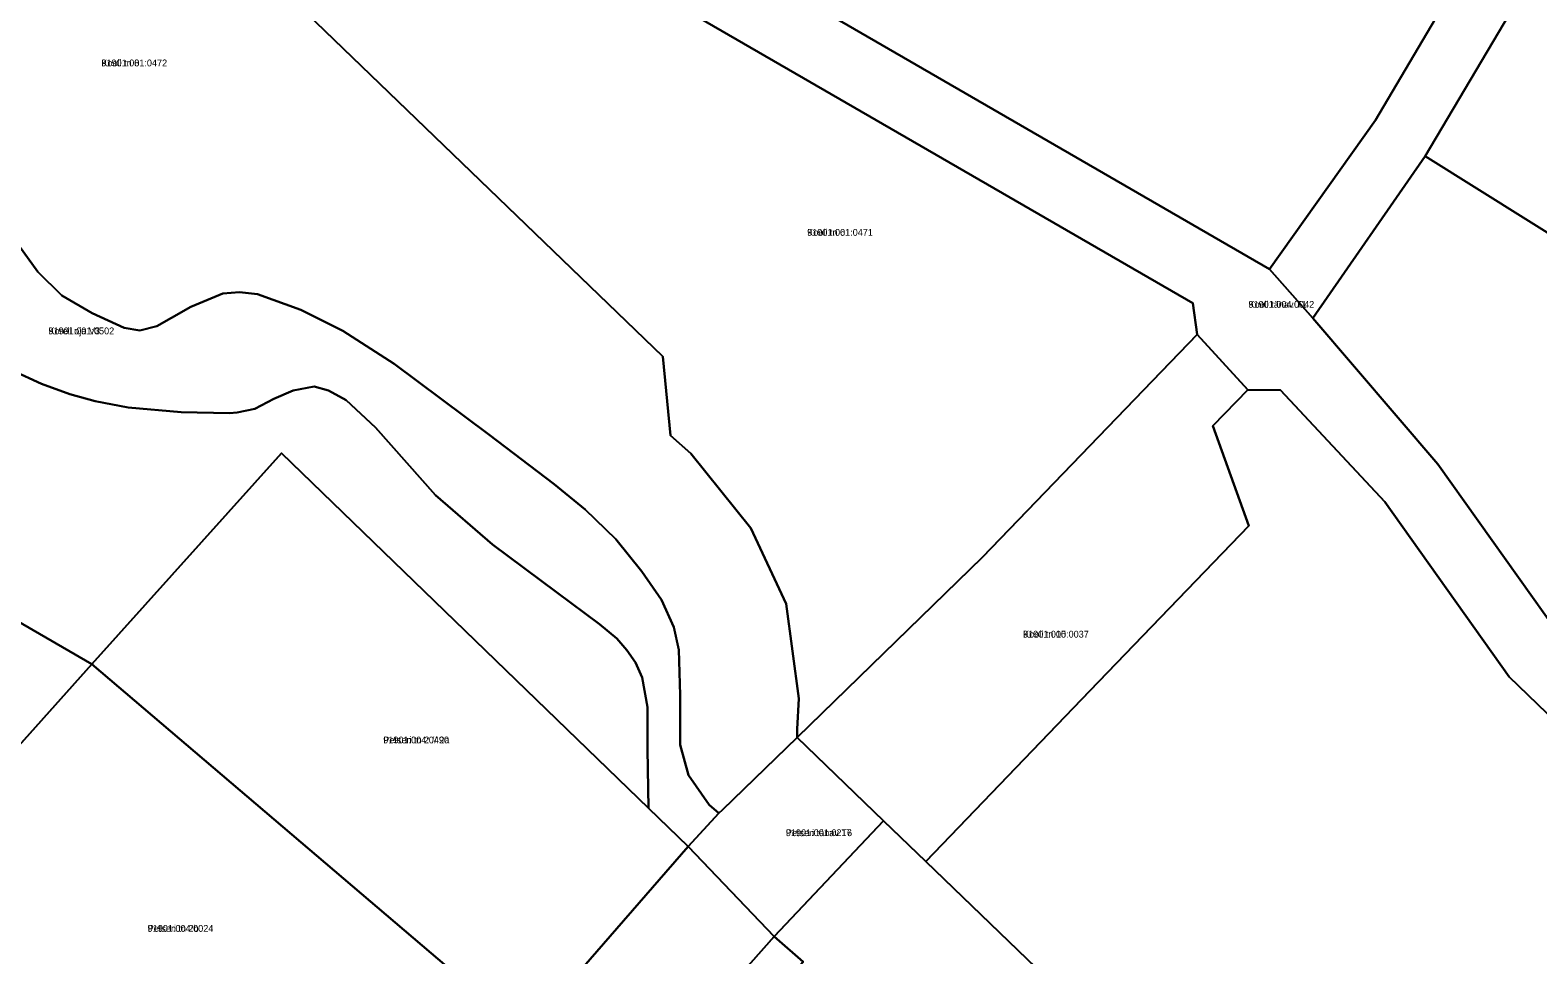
# Model space of a CAD drawing. Extents: x 675810 to 681273, y 6411190 to 6417565.
# Drawn here: x 678420.5 to 678753.1, y 6415433.8 to 6415637.7 of the extents above; entities that cross this region are included whole.
import ezdxf

# ---------------------------------------------------------------- set-up
doc = ezdxf.new("R2010")
doc.units = 0
for name, color, linetype in [('L_AADRESS', 7, 'Continuous'), ('PIIR', 7, 'Continuous'), ('TUNNUS', 7, 'Continuous')]:
    doc.layers.add(name, color=color, linetype=linetype)

msp = doc.modelspace()

# ---------------------------------------------------------------- linework, layer by layer
at = {"layer": 'PIIR'}
for points in [[(678717.31, 6415617.85), (678693.89, 6415584.98), (678536.61, 6415675.95), (678527.82, 6415691.55), (678599.64, 6415810.83), (678613.08, 6415812.33), (678614.18, 6415808.05), (678621.93, 6415778.52), (678657.45, 6415759.12), (678662.54, 6415756.35), (678693.95, 6415739.26), (678709.19, 6415730.96), (678765.39, 6415700.27), (678765.87, 6415700.01)], [(678459.31, 6415662.82), (678502.14, 6415702.96), (678522.6, 6415666.75), (678677, 6415577.51), (678677.93, 6415570.6), (678630.57, 6415521.46), (678589.7, 6415481.71), (678589.71, 6415483.49), (678590.11, 6415490.25), (678587.29, 6415511.18), (678579.49, 6415527.84), (678566.22, 6415544.29), (678561.73, 6415548.27), (678560.09, 6415565.74)], [(678765.87, 6415700.01), (678772.39, 6415696.39), (678777.6, 6415693.42), (678757.94, 6415660.15), (678783.06, 6415644.39), (678794.13, 6415637.17), (678787.76, 6415627.4), (678751.91, 6415649.88), (678728.29, 6415609.9), (678703.45, 6415574.17), (678693.89, 6415584.98), (678717.31, 6415617.85)], [(678751.91, 6415649.88), (678787.76, 6415627.4), (678762.45, 6415588.51), (678728.29, 6415609.9)], [(678728.29, 6415609.9), (678762.45, 6415588.51), (678793.29, 6415569.17), (678788.17, 6415560.57), (678766.76, 6415526.38), (678818.37, 6415494.02), (678799.97, 6415464.74), (678757.76, 6415504.49), (678731.08, 6415541.99), (678703.45, 6415574.17)], [(678677.93, 6415570.6), (678689.11, 6415558.37), (678681.42, 6415550.39), (678689.39, 6415528.39), (678654.27, 6415491.95), (678618.06, 6415454.35), (678608.76, 6415463.31), (678589.7, 6415481.71), (678630.57, 6415521.46)], [(678529.76, 6415416.4), (678434.11, 6415497.88), (678475.9, 6415544.38), (678556.91, 6415466.12), (678565.67, 6415457.65)], [(678402.16, 6415516.32), (678434.11, 6415497.88), (678405.4, 6415465.9), (678389.48, 6415480.64), (678381.04, 6415471.59), (678369.49, 6415483.78)], [(678434.11, 6415497.88), (678529.76, 6415416.4), (678497.75, 6415379.78), (678473.98, 6415399.41), (678456.97, 6415380.5), (678442.3, 6415393.23), (678424.47, 6415408.59), (678402.71, 6415427.34), (678384.39, 6415443.11), (678370.48, 6415455.37), (678368.05, 6415457.5), (678381.04, 6415471.59), (678389.48, 6415480.64), (678405.4, 6415465.9)], [(678589.7, 6415481.71), (678608.76, 6415463.31), (678584.63, 6415437.83), (678565.67, 6415457.65), (678572.45, 6415464.96), (678573.21, 6415465.7)], [(678584.63, 6415437.83), (678608.76, 6415463.31), (678618.06, 6415454.35), (678662.7, 6415411.33), (678659.2, 6415407.69), (678682.83, 6415382.78), (678788.36, 6415281.11), (678802.18, 6415256.98), (678673.64, 6415238.7), (678714.53, 6415285.6), (678721.11, 6415293.41), (678720.4, 6415306.05), (678710.92, 6415314.87), (678711.4, 6415315.4), (678675.46, 6415348.99), (678631.26, 6415386.89), (678595.98, 6415417.47), (678585.87, 6415405.7), (678577.83, 6415417.22), (678591.06, 6415432.23)], [(678565.67, 6415457.65), (678584.63, 6415437.83), (678571.47, 6415422.91), (678577.83, 6415417.22), (678585.87, 6415405.7), (678566.01, 6415382.6), (678560.85, 6415376.6), (678533.42, 6415400.18), (678488.18, 6415348.7), (678464.2, 6415322.7), (678452.22, 6415309.34), (678433.25, 6415288.62), (678405.25, 6415257.4), (678395.92, 6415265.33), (678410.29, 6415281.72), (678428.69, 6415301.59), (678442, 6415316.83), (678453.58, 6415329.69), (678458.78, 6415334.97), (678482.4, 6415362.13), (678497.75, 6415379.78), (678529.76, 6415416.4)], [(678571.47, 6415422.91), (678584.63, 6415437.83), (678591.06, 6415432.23), (678577.83, 6415417.22)]]:
    msp.add_lwpolyline(points, close=True, dxfattribs=at)
for points in [[(678536.61, 6415675.95), (678693.89, 6415584.98), (678703.45, 6415574.17), (678731.08, 6415541.99), (678757.76, 6415504.49)], [(678771.76, 6415471.03), (678746.79, 6415495.08), (678719.35, 6415533.64), (678696.36, 6415558.3), (678689.11, 6415558.37), (678677.93, 6415570.6), (678677, 6415577.51), (678522.6, 6415666.75)], [(678459.31, 6415662.82), (678560.09, 6415565.74), (678561.73, 6415548.27), (678566.22, 6415544.29), (678579.49, 6415527.84), (678587.29, 6415511.18), (678590.11, 6415490.25), (678589.71, 6415483.49), (678589.7, 6415481.71), (678573.21, 6415465.7), (678572.45, 6415464.96), (678570.29, 6415466.86), (678565.73, 6415473.4), (678563.93, 6415480.05), (678563.9, 6415491.02), (678563.62, 6415501.05), (678562.51, 6415506.01), (678559.78, 6415512.05), (678555.4, 6415518.28), (678549.68, 6415525.43), (678542.95, 6415531.96), (678536.11, 6415537.58), (678521.66, 6415548.54), (678500.79, 6415564.07), (678489.45, 6415571.4), (678480.2, 6415575.98), (678470.61, 6415579.43), (678466.69, 6415579.87), (678462.96, 6415579.58), (678455.96, 6415576.7), (678451.68, 6415574.27), (678448.46, 6415572.37), (678444.68, 6415571.44), (678441.23, 6415572.02), (678434.17, 6415575.28), (678427.44, 6415579.17), (678422.19, 6415584.38), (678416.07, 6415592.85)], [(678416.07, 6415592.85), (678422.19, 6415584.38), (678427.44, 6415579.17), (678434.17, 6415575.28), (678441.23, 6415572.02), (678444.68, 6415571.44), (678448.46, 6415572.37), (678451.68, 6415574.27), (678455.96, 6415576.7), (678462.96, 6415579.58), (678466.69, 6415579.87), (678470.61, 6415579.43), (678480.2, 6415575.98), (678489.45, 6415571.4), (678500.79, 6415564.07), (678521.66, 6415548.54), (678536.11, 6415537.58), (678542.95, 6415531.96), (678549.68, 6415525.43), (678555.4, 6415518.28), (678559.78, 6415512.05), (678562.51, 6415506.01), (678563.62, 6415501.05), (678563.9, 6415491.02), (678563.93, 6415480.05), (678565.73, 6415473.4), (678570.29, 6415466.86), (678572.45, 6415464.96), (678565.67, 6415457.65), (678556.91, 6415466.12), (678556.7, 6415479.11), (678556.69, 6415488.36), (678555.54, 6415494.93), (678554.01, 6415498.2), (678552.12, 6415500.97), (678549.91, 6415503.55), (678546.13, 6415506.66), (678536.63, 6415513.72), (678522.52, 6415524.28), (678509.89, 6415535.13), (678503.61, 6415542.24), (678496.69, 6415550.03), (678490.19, 6415556.06), (678486.28, 6415558.2), (678483.14, 6415559.08), (678478.54, 6415558.2), (678474.25, 6415556.39), (678470.06, 6415554.2), (678466.16, 6415553.36), (678464.48, 6415553.18), (678453.81, 6415553.42), (678442.11, 6415554.44), (678434.85, 6415555.88), (678429.22, 6415557.44), (678423.02, 6415559.69), (678416.57, 6415562.63)], [(678416.57, 6415562.63), (678423.02, 6415559.69), (678429.22, 6415557.44), (678434.85, 6415555.88), (678442.11, 6415554.44), (678453.81, 6415553.42), (678464.48, 6415553.18), (678466.16, 6415553.36), (678470.06, 6415554.2), (678474.25, 6415556.39), (678478.54, 6415558.2), (678483.14, 6415559.08), (678486.28, 6415558.2), (678490.19, 6415556.06), (678496.69, 6415550.03), (678503.61, 6415542.24), (678509.89, 6415535.13), (678522.52, 6415524.28), (678536.63, 6415513.72), (678546.13, 6415506.66), (678549.91, 6415503.55), (678552.12, 6415500.97), (678554.01, 6415498.2), (678555.54, 6415494.93), (678556.69, 6415488.36), (678556.7, 6415479.11), (678556.91, 6415466.12), (678475.9, 6415544.38), (678434.11, 6415497.88), (678402.16, 6415516.32)], [(678788.36, 6415281.11), (678682.83, 6415382.78), (678659.2, 6415407.69), (678662.7, 6415411.33), (678618.06, 6415454.35), (678654.27, 6415491.95), (678689.39, 6415528.39), (678681.42, 6415550.39), (678689.11, 6415558.37), (678696.36, 6415558.3), (678719.35, 6415533.64), (678746.79, 6415495.08), (678771.76, 6415471.03)]]:
    msp.add_lwpolyline(points, dxfattribs=at)

# ---------------------------------------------------------------- texts
at = {"layer": 'L_AADRESS'}
for s, p in [('Kooli tn 8', (678436.2, 6415629.71)), ('Kooli tn 6', (678591.92, 6415592.34)), ('Kooli tänav T1', (678689.29, 6415576.46)), ('Koreli oja V3', (678424.52, 6415570.61)), ('Kooli tn 10', (678639.55, 6415503.72)), ('Petseri tn 2 // 2a', (678498.39, 6415480.39)), ('Petseri tänav T6', (678587.21, 6415459.93)), ('Petseri tn 2b', (678446.4, 6415438.83))]:
    msp.add_text(s, height=1.5, dxfattribs=at).set_placement(p)
at = {"layer": 'TUNNUS'}
for s, p in [('91901:001:0472', (678436.2, 6415629.71)), ('91901:001:0471', (678591.92, 6415592.34)), ('91901:004:0042', (678689.29, 6415576.46)), ('91901:001:0502', (678424.52, 6415570.61)), ('91901:005:0037', (678639.55, 6415503.72)), ('91901:004:0490', (678498.39, 6415480.39)), ('91901:001:0217', (678587.21, 6415459.93)), ('91901:004:0024', (678446.4, 6415438.83))]:
    msp.add_text(s, height=1.5, dxfattribs=at).set_placement(p)

doc.saveas('drawing.dxf')
